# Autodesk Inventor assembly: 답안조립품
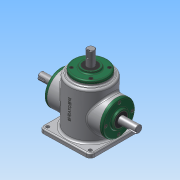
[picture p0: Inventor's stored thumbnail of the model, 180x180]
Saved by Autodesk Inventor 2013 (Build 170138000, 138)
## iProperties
Created: 2015-10
Part Number: 답안조립품
Document SubType Name: Assembly
Designer: Administrator
Author: Administrator
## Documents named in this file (14)
- C:\Users\Administrator\Desktop\451008V1021\답안조립품.iam
- C:\Users\Administrator\Desktop\451008V1021\1-본체.ipt
- C:\Users\Administrator\Desktop\451008V1021\베어링 6203.ipt
- C:\Users\Administrator\Desktop\451008V1021\메인 축.ipt
- 메인 축.ipt
- C:\Users\Administrator\Desktop\451008V1021\키 5x5.ipt
- C:\Users\Administrator\Desktop\451008V1021\메인 베벨기어.ipt
- C:\Users\Administrator\Desktop\451008V1021\커버.ipt
- C:\Users\Administrator\Desktop\451008V1021\M4.ipt
- C:\Users\Administrator\Desktop\451008V1021\오일실.ipt
- C:\Users\Administrator\Desktop\451008V1021\서브 베벨기어.ipt
- C:\Users\Administrator\Desktop\451008V1021\서브 축.ipt
- 서브 축.ipt
- C:\Users\Administrator\Desktop\451008V1021\키 4x4.ipt
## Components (13 placed, 2 different names)
1. 1-본체:1
2. M4:1
3. M4:3
4. M4:4
5. M4:5
6. M4:2
7. M4:6
8. M4:7
9. M4:8
10. M4:9
11. M4:10
12. M4:11
13. M4:12
